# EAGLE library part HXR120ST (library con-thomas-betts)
THOMAS&BETTS
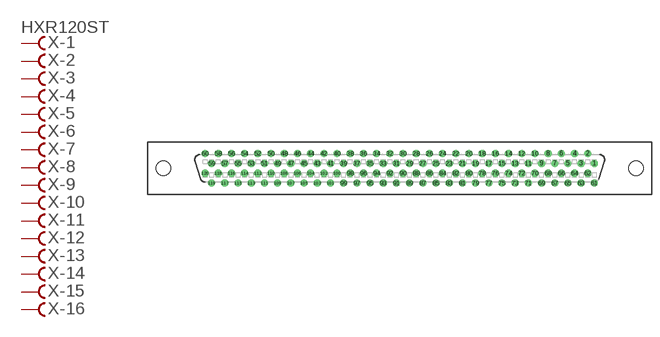
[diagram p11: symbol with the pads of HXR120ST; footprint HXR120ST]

Designator prefix X; gates -1=FV -2=F -3=F -4=F -5=F -6=F -7=F -8=F -9=F -10=F -11=F -12=F -13=F -14=F -15=F -16=F -17=F -18=F -19=F -20=F -21=F -22=F -23=F -24=F -25=F -26=F -27=F -28=F -29=F -30=F -31=F -32=F -33=F -34=F -35=F -36=F -37=F -38=F -39=F -40=F -41=F -42=F -43=F -44=F -45=F -46=F -47=F -48=F -49=F -50=F -51=F -52=F -53=F -54=F -55=F -56=F -57=F -58=F -59=F -60=F -61=F -62=F -63=F -64=F -65=F -66=F -67=F -68=F -69=F -70=F -71=F -72=F -73=F -74=F -75=F -76=F -77=F -78=F -79=F -80=F -81=F -82=F -83=F -84=F -85=F -86=F -87=F -88=F -89=F -90=F -91=F -92=F -93=F -94=F -95=F -96=F -97=F -98=F -99=F -100=F -101=F -102=F -103=F -104=F -105=F -106=F -107=F -108=F -109=F -110=F -111=F -112=F -113=F -114=F -115=F -116=F -117=F -118=F -119=F -120=F

## HXR120ST (OC_FARNELL: unknown; OC_NEWARK: unknown)  [HXR120ST]
1  -1:F  pas
2  -2:F  pas
3  -3:F  pas
4  -4:F  pas
5  -5:F  pas
6  -6:F  pas
7  -7:F  pas
8  -8:F  pas
9  -9:F  pas
10  -10:F  pas
11  -11:F  pas
12  -12:F  pas
13  -13:F  pas
14  -14:F  pas
15  -15:F  pas
16  -16:F  pas
17  -17:F  pas
18  -18:F  pas
19  -19:F  pas
20  -20:F  pas
21  -21:F  pas
22  -22:F  pas
23  -23:F  pas
24  -24:F  pas
25  -25:F  pas
26  -26:F  pas
27  -27:F  pas
28  -28:F  pas
29  -29:F  pas
30  -30:F  pas
31  -31:F  pas
32  -32:F  pas
33  -33:F  pas
34  -34:F  pas
35  -35:F  pas
36  -36:F  pas
37  -37:F  pas
38  -38:F  pas
39  -39:F  pas
40  -40:F  pas
41  -41:F  pas
42  -42:F  pas
43  -43:F  pas
44  -44:F  pas
45  -45:F  pas
46  -46:F  pas
47  -47:F  pas
48  -48:F  pas
49  -49:F  pas
50  -50:F  pas
51  -51:F  pas
52  -52:F  pas
53  -53:F  pas
54  -54:F  pas
55  -55:F  pas
56  -56:F  pas
57  -57:F  pas
58  -58:F  pas
59  -59:F  pas
60  -60:F  pas
61  -61:F  pas
62  -62:F  pas
63  -63:F  pas
64  -64:F  pas
65  -65:F  pas
66  -66:F  pas
67  -67:F  pas
68  -68:F  pas
69  -69:F  pas
70  -70:F  pas
71  -71:F  pas
72  -72:F  pas
73  -73:F  pas
74  -74:F  pas
75  -75:F  pas
76  -76:F  pas
77  -77:F  pas
78  -78:F  pas
79  -79:F  pas
80  -80:F  pas
81  -81:F  pas
82  -82:F  pas
83  -83:F  pas
84  -84:F  pas
85  -85:F  pas
86  -86:F  pas
87  -87:F  pas
88  -88:F  pas
89  -89:F  pas
90  -90:F  pas
91  -91:F  pas
92  -92:F  pas
93  -93:F  pas
94  -94:F  pas
95  -95:F  pas
96  -96:F  pas
97  -97:F  pas
98  -98:F  pas
99  -99:F  pas
100  -100:F  pas
101  -101:F  pas
102  -102:F  pas
103  -103:F  pas
104  -104:F  pas
105  -105:F  pas
106  -106:F  pas
107  -107:F  pas
108  -108:F  pas
109  -109:F  pas
110  -110:F  pas
111  -111:F  pas
112  -112:F  pas
113  -113:F  pas
114  -114:F  pas
115  -115:F  pas
116  -116:F  pas
117  -117:F  pas
118  -118:F  pas
119  -119:F  pas
120  -120:F  pas

## Footprint HXR120ST (pad centres in mm)
THOMAS&BETTS HFR120ST29xx, HHR120ST29xx
drill 0.864 octagon: 1 37.465,0.953
drill 0.864 round: 2 36.195,2.857; 3 34.925,0.953; 4 33.655,2.857; 5 32.385,0.953; 6 31.115,2.857; 7 29.845,0.953; 8 28.575,2.857; 9 27.305,0.953; 10 26.035,2.857; 11 24.765,0.953; 12 23.495,2.857; 13 22.225,0.953; 14 20.955,2.857; 15 19.685,0.953; 16 18.415,2.857; 17 17.145,0.953; 18 15.875,2.857; 19 14.605,0.953; 20 13.335,2.857; 21 12.065,0.953; 22 10.795,2.857; 23 9.525,0.953; 24 8.255,2.857; 25 6.985,0.953; 26 5.715,2.857; 27 4.445,0.953; 28 3.175,2.857; 29 1.905,0.953; 30 0.635,2.857; 31 -0.635,0.953; 32 -1.905,2.857; 33 -3.175,0.953; 34 -4.445,2.857; 35 -5.715,0.953; 36 -6.985,2.857; 37 -8.255,0.953; 38 -9.525,2.857; 39 -10.795,0.953; 40 -12.065,2.857; 41 -13.335,0.953; 42 -14.605,2.857; 43 -15.875,0.953; 44 -17.145,2.857; 45 -18.415,0.953; 46 -19.685,2.857; 47 -20.955,0.953; 48 -22.225,2.857; 49 -23.495,0.953; 50 -24.765,2.857; 51 -26.035,0.953; 52 -27.305,2.857; 53 -28.575,0.953; 54 -29.845,2.857; 55 -31.115,0.953; 56 -32.385,2.857; 57 -33.655,0.953; 58 -34.925,2.857; 59 -36.195,0.953; 60 -37.465,2.857; 61 37.465,-2.857; 62 36.195,-0.953; 63 34.925,-2.857; 64 33.655,-0.953; 65 32.385,-2.857; 66 31.115,-0.953; 67 29.845,-2.857; 68 28.575,-0.953; 69 27.305,-2.857; 70 26.035,-0.953; 71 24.765,-2.857; 72 23.495,-0.953; 73 22.225,-2.857; 74 20.955,-0.953; 75 19.685,-2.857; 76 18.415,-0.953; 77 17.145,-2.857; 78 15.875,-0.953; 79 14.605,-2.857; 80 13.335,-0.953; 81 12.065,-2.857; 82 10.795,-0.953; 83 9.525,-2.857; 84 8.255,-0.953; 85 6.985,-2.857; 86 5.715,-0.953; 87 4.445,-2.857; 88 3.175,-0.953; 89 1.905,-2.857; 90 0.635,-0.953; 91 -0.635,-2.857; 92 -1.905,-0.953; 93 -3.175,-2.857; 94 -4.445,-0.953; 95 -5.715,-2.857; 96 -6.985,-0.953; 97 -8.255,-2.857; 98 -9.525,-0.953; 99 -10.795,-2.857; 100 -12.065,-0.953; 101 -13.335,-2.857; 102 -14.605,-0.953; 103 -15.875,-2.857; 104 -17.145,-0.953; 105 -18.415,-2.857; 106 -19.685,-0.953; 107 -20.955,-2.857; 108 -22.225,-0.953; 109 -23.495,-2.857; 110 -24.765,-0.953; 111 -26.035,-2.857; 112 -27.305,-0.953; 113 -28.575,-2.857; 114 -29.845,-0.953; 115 -31.115,-2.857; 116 -32.385,-0.953; 117 -33.655,-2.857; 118 -34.925,-0.953; 119 -36.195,-2.857; 120 -37.465,-0.953
hole 2.769 at 45.466,0.013
hole 2.769 at -45.466,0.013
